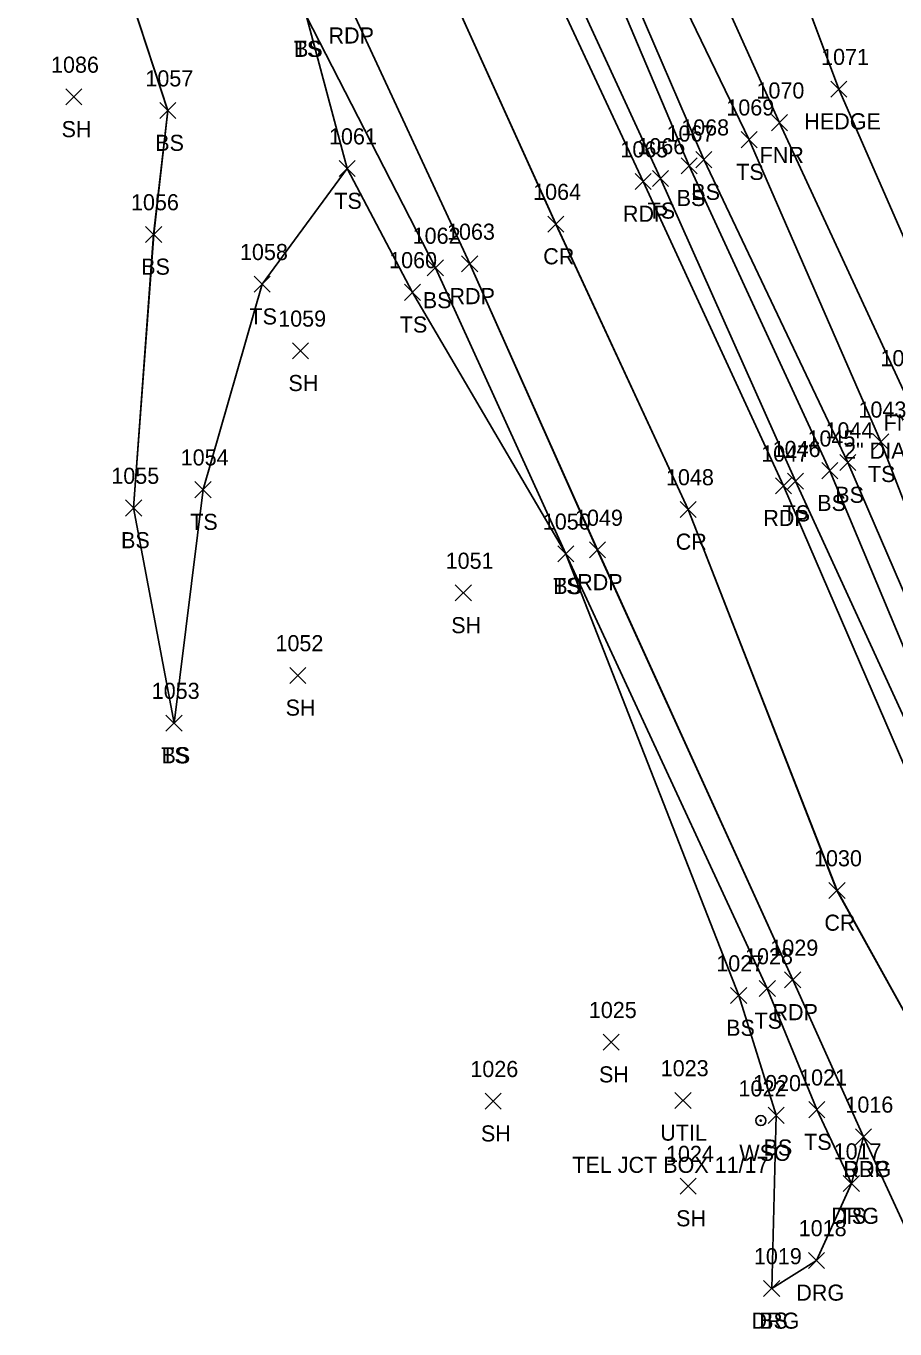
# Model space of a CAD drawing. Extents: x 1415642 to 1422021, y 544543 to 547232.
# Drawn here: x 1416485.4 to 1416593.3, y 546172.7 to 546334.5 of the extents above; entities that cross this region are included whole.
import ezdxf

# ---------------------------------------------------------------- set-up
doc = ezdxf.new("R2010")
doc.units = 0
for name, color, linetype in [('L_A', 7, 'Continuous'), ('L_I', 7, 'Continuous'), ('L_TIC', 7, 'Continuous'), ('LAHR', 7, 'Continuous'), ('LELB', 7, 'Continuous'), ('LFNC', 7, 'Continuous'), ('M_C', 7, 'Continuous'), ('P_A', 7, 'Continuous'), ('P_I', 7, 'Continuous'), ('P_TIC', 7, 'Continuous'), ('PET', 7, 'Continuous'), ('PRC', 7, 'Continuous'), ('R_A', 7, 'Continuous'), ('R_I', 7, 'Continuous'), ('R_TIC', 7, 'Continuous'), ('RDG', 7, 'Continuous'), ('U_A', 7, 'Continuous'), ('U_C', 7, 'Continuous'), ('U_I', 7, 'Continuous'), ('UDEFAULT', 7, 'Continuous'), ('UWV', 7, 'Continuous')]:
    doc.layers.add(name, color=color, linetype=linetype)

msp = doc.modelspace()

# ---------------------------------------------------------------- linework, layer by layer
at = {"layer": 'L_TIC'}
for points in [[(1416585.35, 546325.71), (1416587.35, 546327.71)], [(1416587.35, 546325.71), (1416585.35, 546327.71)], [(1416490.31, 546324.74), (1416492.31, 546326.74)], [(1416492.31, 546324.74), (1416490.31, 546326.74)], [(1416501.98, 546323.04), (1416503.98, 546325.04)], [(1416503.98, 546323.04), (1416501.98, 546325.04)], [(1416577.97, 546321.54), (1416579.97, 546323.54)], [(1416579.97, 546321.54), (1416577.97, 546323.54)], [(1416574.19, 546319.43), (1416576.19, 546321.43)], [(1416576.19, 546319.43), (1416574.19, 546321.43)], [(1416524.26, 546315.84), (1416526.26, 546317.84)], [(1416526.26, 546315.84), (1416524.26, 546317.84)], [(1416524.26, 546315.84), (1416526.26, 546317.84)], [(1416526.26, 546315.84), (1416524.26, 546317.84)], [(1416566.76, 546316.19), (1416568.76, 546318.19)], [(1416568.76, 546316.19), (1416566.76, 546318.19)], [(1416568.58, 546316.95), (1416570.58, 546318.95)], [(1416570.58, 546316.95), (1416568.58, 546318.95)], [(1416563.18, 546314.62), (1416565.18, 546316.62)], [(1416565.18, 546314.62), (1416563.18, 546316.62)], [(1416500.23, 546307.66), (1416502.23, 546309.66)], [(1416502.23, 546307.66), (1416500.23, 546309.66)], [(1416535.22, 546303.5), (1416537.22, 546305.5)], [(1416537.22, 546303.5), (1416535.22, 546305.5)], [(1416513.72, 546301.48), (1416515.72, 546303.48)], [(1416515.72, 546301.48), (1416513.72, 546303.48)], [(1416532.39, 546300.47), (1416534.39, 546302.47)], [(1416534.39, 546300.47), (1416532.39, 546302.47)], [(1416518.48, 546293.21), (1416520.48, 546295.21)], [(1416520.48, 546293.21), (1416518.48, 546295.21)], [(1416590.55, 546281.91), (1416592.55, 546283.91)], [(1416592.55, 546281.91), (1416590.55, 546283.91)], [(1416586.46, 546279.33), (1416588.46, 546281.33)], [(1416588.46, 546279.33), (1416586.46, 546281.33)], [(1416579.95, 546277.02), (1416581.95, 546279.02)], [(1416581.95, 546277.02), (1416579.95, 546279.02)], [(1416584.22, 546278.32), (1416586.22, 546280.32)], [(1416586.22, 546278.32), (1416584.22, 546280.32)], [(1416506.36, 546275.97), (1416508.36, 546277.97)], [(1416508.36, 546275.97), (1416506.36, 546277.97)], [(1416497.74, 546273.69), (1416499.74, 546275.69)], [(1416499.74, 546273.69), (1416497.74, 546275.69)], [(1416551.43, 546268), (1416553.43, 546270)], [(1416553.43, 546268), (1416551.43, 546270)], [(1416551.43, 546268), (1416553.43, 546270)], [(1416553.43, 546268), (1416551.43, 546270)], [(1416538.7, 546263.14), (1416540.7, 546265.14)], [(1416540.7, 546263.14), (1416538.7, 546265.14)], [(1416518.13, 546252.9), (1416520.13, 546254.9)], [(1416520.13, 546252.9), (1416518.13, 546254.9)], [(1416502.76, 546246.98), (1416504.76, 546248.98)], [(1416504.76, 546246.98), (1416502.76, 546248.98)], [(1416502.76, 546246.98), (1416504.76, 546248.98)], [(1416504.76, 546246.98), (1416502.76, 546248.98)], [(1416576.46, 546214.02), (1416578.46, 546216.02)], [(1416578.46, 546214.02), (1416576.46, 546216.02)], [(1416572.9, 546213.14), (1416574.9, 546215.14)], [(1416574.9, 546213.14), (1416572.9, 546215.14)], [(1416557.07, 546207.35), (1416559.07, 546209.35)], [(1416559.07, 546207.35), (1416557.07, 546209.35)], [(1416542.39, 546200.02), (1416544.39, 546202.02)], [(1416544.39, 546200.02), (1416542.39, 546202.02)], [(1416577.55, 546198.27), (1416579.55, 546200.27)], [(1416579.55, 546198.27), (1416577.55, 546200.27)], [(1416582.62, 546198.97), (1416584.62, 546200.97)], [(1416584.62, 546198.97), (1416582.62, 546200.97)], [(1416586.9, 546189.79), (1416588.9, 546191.79)], [(1416588.9, 546189.79), (1416586.9, 546191.79)], [(1416566.64, 546189.48), (1416568.64, 546191.48)], [(1416568.64, 546189.48), (1416566.64, 546191.48)], [(1416577, 546176.77), (1416579, 546178.77)], [(1416579, 546176.77), (1416577, 546178.77)]]:
    msp.add_lwpolyline(points, dxfattribs=at)
at = {"layer": 'LAHR'}
for points in [[(1416601.24, 546292.69), (1416586.35, 546326.71), (1416573.12, 546362.04), (1416558.49, 546390.29), (1416537.49, 546434.36), (1416523.93, 546467.1), (1416523.32, 546471.61)], [(1416601.24, 546292.69), (1416586.35, 546326.71), (1416573.12, 546362.03), (1416558.49, 546390.29), (1416537.49, 546434.36), (1416523.93, 546467.1), (1416523.32, 546471.61)]]:
    msp.add_lwpolyline(points, dxfattribs=at)
at = {"layer": 'LELB'}
for points in [[(1416578, 546177.77), (1416578.55, 546199.27), (1416573.9, 546214.14), (1416552.43, 546269), (1416536.22, 546304.5), (1416520.22, 546335.71), (1416500.65, 546371.21), (1416484.25, 546405.14), (1416455.06, 546455.78), (1416435.93, 546486.65), (1416412.14, 546519.01), (1416383.64, 546557.13), (1416352.74, 546592.54), (1416331.82, 546618.14), (1416293.94, 546655.61), (1416274.22, 546680.91), (1416245.72, 546708.98), (1416224.27, 546729.93), (1416198.14, 546753.3), (1416170.94, 546765.48), (1416158.5, 546767.31), (1416141.08, 546772.75), (1416136.01, 546776.95), (1416129, 546780.64)], [(1416578, 546177.77), (1416578.55, 546199.27), (1416573.9, 546214.14), (1416552.42, 546269.01), (1416536.22, 546304.5), (1416520.22, 546335.71), (1416500.65, 546371.22), (1416484.25, 546405.15), (1416455.06, 546455.79), (1416435.93, 546486.65), (1416412.14, 546519.01), (1416383.65, 546557.13), (1416352.74, 546592.54), (1416331.82, 546618.14), (1416293.94, 546655.62), (1416274.22, 546680.91), (1416245.72, 546708.98), (1416224.27, 546729.93), (1416198.14, 546753.3), (1416170.94, 546765.48), (1416158.51, 546767.31), (1416141.09, 546772.75), (1416136.01, 546776.96), (1416129.01, 546780.64)], [(1416503.76, 546247.98), (1416498.74, 546274.69), (1416501.23, 546308.66), (1416502.98, 546324.04), (1416489.47, 546365.32), (1416480.57, 546403.46), (1416453.11, 546455.02), (1416433.2, 546484.78), (1416409.26, 546516.78), (1416378.25, 546552.92), (1416343.61, 546583.91), (1416327.57, 546614.09), (1416289.4, 546651.59), (1416267.58, 546675.69), (1416237.14, 546697.31), (1416220.66, 546725.9), (1416195.41, 546750.9), (1416170.78, 546763.33), (1416158.82, 546764.49), (1416140.16, 546770.72), (1416135.4, 546775.05), (1416128.27, 546778.63)], [(1416503.76, 546247.98), (1416498.74, 546274.69), (1416501.24, 546308.65), (1416502.98, 546324.03), (1416489.47, 546365.32), (1416480.57, 546403.46), (1416453.11, 546455.02), (1416433.2, 546484.78), (1416409.26, 546516.79), (1416378.25, 546552.92), (1416343.61, 546583.91), (1416327.58, 546614.09), (1416289.4, 546651.59), (1416267.58, 546675.69), (1416237.14, 546697.31), (1416220.66, 546725.9), (1416195.42, 546750.9), (1416170.78, 546763.33), (1416158.81, 546764.5), (1416140.16, 546770.72), (1416135.4, 546775.05), (1416128.28, 546778.62)], [(1416587.9, 546190.79), (1416583.62, 546199.97), (1416577.46, 546215.02), (1416552.43, 546269), (1416533.39, 546301.47), (1416525.26, 546316.84), (1416520.22, 546335.71), (1416504.13, 546372.91), (1416486.87, 546406.07), (1416456.87, 546456.96), (1416435.93, 546486.65), (1416413.88, 546519.84), (1416385.73, 546558.12)], [(1416587.91, 546190.79), (1416583.61, 546199.97), (1416577.46, 546215.02), (1416552.42, 546269.01), (1416533.39, 546301.47), (1416525.26, 546316.84), (1416520.22, 546335.71), (1416504.13, 546372.91), (1416486.87, 546406.07), (1416456.87, 546456.96), (1416435.93, 546486.65), (1416413.88, 546519.84), (1416385.73, 546558.12)], [(1416624.83, 546188.33), (1416609.68, 546228.85), (1416587.46, 546280.33), (1416569.58, 546317.95), (1416555.08, 546351.62), (1416539.63, 546384.17), (1416546.45, 546386.59), (1416544.38, 546389.65), (1416537.72, 546389.11), (1416521.41, 546422.69), (1416507.02, 546457.32), (1416500.86, 546474.51), (1416499.33, 546475.96), (1416498.77, 546475.76), (1416499.17, 546473.82)], [(1416624.83, 546188.34), (1416609.68, 546228.85), (1416587.45, 546280.34), (1416569.58, 546317.95), (1416555.08, 546351.63), (1416539.63, 546384.17), (1416546.45, 546386.59), (1416544.38, 546389.64), (1416537.72, 546389.12), (1416521.42, 546422.68), (1416507.02, 546457.32), (1416500.87, 546474.51), (1416499.33, 546475.96), (1416498.77, 546475.76), (1416499.17, 546473.83)], [(1416624.13, 546188.48), (1416606.9, 546227.58), (1416585.22, 546279.32), (1416567.76, 546317.19), (1416553.66, 546350.45), (1416534.43, 546386.06), (1416517.2, 546422.02), (1416505.52, 546457.03), (1416499.17, 546473.83)], [(1416624.13, 546188.48), (1416606.9, 546227.58), (1416585.22, 546279.32), (1416567.76, 546317.19), (1416553.66, 546350.45), (1416534.43, 546386.06), (1416517.2, 546422.01), (1416505.52, 546457.03), (1416499.17, 546473.82)], [(1416620.93, 546187.09), (1416604.47, 546226.81), (1416580.95, 546278.02), (1416564.18, 546315.62), (1416549.05, 546348.52), (1416530.53, 546385.22), (1416512.89, 546419.96), (1416490.18, 546459.78)], [(1416620.93, 546187.09), (1416604.48, 546226.8), (1416580.95, 546278.02), (1416564.18, 546315.62), (1416549.05, 546348.51), (1416530.53, 546385.22), (1416512.89, 546419.96), (1416490.18, 546459.78)], [(1416632.67, 546189.86), (1416612.14, 546229.74), (1416591.55, 546282.91), (1416575.19, 546320.43), (1416559.06, 546353.84), (1416543.37, 546383.11), (1416547.74, 546382.96), (1416548.95, 546386.35)], [(1416632.67, 546189.86), (1416612.15, 546229.74), (1416591.55, 546282.91), (1416575.19, 546320.43), (1416559.06, 546353.84), (1416543.37, 546383.11), (1416547.74, 546382.97), (1416548.95, 546386.35)], [(1416503.76, 546247.98), (1416507.36, 546276.97), (1416514.72, 546302.48), (1416525.26, 546316.84)], [(1416503.76, 546247.98), (1416507.37, 546276.97), (1416514.72, 546302.48), (1416525.26, 546316.84)]]:
    msp.add_lwpolyline(points, dxfattribs=at)
at = {"layer": 'LFNC'}
for points in [[(1416616.17, 546291.53), (1416602.64, 546290.41), (1416594.37, 546289.3), (1416578.97, 546322.54), (1416563.77, 546356.27), (1416548.95, 546386.35), (1416547.3, 546389.95), (1416530.29, 546426.68), (1416513.55, 546462.2), (1416508.34, 546472.94), (1416504.48, 546483), (1416512.48, 546489.98)], [(1416616.17, 546291.53), (1416602.64, 546290.41), (1416594.37, 546289.3), (1416578.97, 546322.54), (1416563.77, 546356.27), (1416548.95, 546386.35), (1416547.3, 546389.95), (1416530.29, 546426.68), (1416513.55, 546462.2), (1416508.35, 546472.93), (1416504.48, 546483), (1416512.48, 546489.98)]]:
    msp.add_lwpolyline(points, dxfattribs=at)
at = {"layer": 'P_TIC'}
for points in [[(1416561.03, 546314.23), (1416563.03, 546316.23)], [(1416563.03, 546314.23), (1416561.03, 546316.23)], [(1416550.19, 546308.95), (1416552.19, 546310.95)], [(1416552.19, 546308.95), (1416550.19, 546310.95)], [(1416539.49, 546304), (1416541.49, 546306)], [(1416541.49, 546304), (1416539.49, 546306)], [(1416578.47, 546276.45), (1416580.47, 546278.45)], [(1416580.47, 546276.45), (1416578.47, 546278.45)], [(1416566.64, 546273.51), (1416568.64, 546275.51)], [(1416568.64, 546273.51), (1416566.64, 546275.51)], [(1416555.35, 546268.48), (1416557.35, 546270.48)], [(1416557.35, 546268.48), (1416555.35, 546270.48)], [(1416585.12, 546226.19), (1416587.12, 546228.19)], [(1416587.12, 546226.19), (1416585.12, 546228.19)], [(1416579.61, 546215.08), (1416581.61, 546217.08)], [(1416581.61, 546215.08), (1416579.61, 546217.08)], [(1416588.42, 546195.6), (1416590.42, 546197.6)], [(1416590.42, 546195.6), (1416588.42, 546197.6)]]:
    msp.add_lwpolyline(points, dxfattribs=at)
at = {"layer": 'PET'}
for points in [[(1416619.56, 546186.67), (1416601.63, 546226.16), (1416579.47, 546277.45), (1416562.03, 546315.23), (1416547.08, 546347.32), (1416527.73, 546384.04), (1416509.97, 546418.47), (1416487.43, 546457.37), (1416462.82, 546495.68), (1416435.56, 546537.44), (1416408.53, 546574.62)], [(1416619.56, 546186.67), (1416601.62, 546226.16), (1416579.47, 546277.45), (1416562.03, 546315.23), (1416547.08, 546347.32), (1416527.73, 546384.03), (1416509.97, 546418.46), (1416487.43, 546457.37), (1416462.82, 546495.68), (1416435.56, 546537.44), (1416408.53, 546574.61)], [(1416599.36, 546175.05), (1416589.42, 546196.6), (1416580.61, 546216.08), (1416556.35, 546269.48), (1416540.49, 546305), (1416525.46, 546337.37), (1416506.55, 546374.02), (1416489.16, 546406.45), (1416459.13, 546457.37), (1416438.7, 546488.16), (1416417.68, 546520.98), (1416388.9, 546560.28)], [(1416599.36, 546175.05), (1416589.42, 546196.6), (1416580.62, 546216.08), (1416556.34, 546269.48), (1416540.49, 546305), (1416525.46, 546337.38), (1416506.55, 546374.02), (1416489.16, 546406.45), (1416459.13, 546457.38), (1416438.7, 546488.17), (1416417.68, 546520.98), (1416388.9, 546560.28)]]:
    msp.add_lwpolyline(points, dxfattribs=at)
at = {"layer": 'PRC'}
for points in [[(1416610.25, 546183.67), (1416586.12, 546227.19), (1416567.64, 546274.51), (1416551.19, 546309.95), (1416536.28, 546342.88), (1416517.21, 546379.83), (1416500.09, 546412.89), (1416469.99, 546464.05), (1416448.59, 546494.95), (1416427.64, 546528.31), (1416425.29, 546532.23), (1416399.16, 546568.17)], [(1416610.26, 546183.67), (1416586.11, 546227.19), (1416567.64, 546274.51), (1416551.18, 546309.96), (1416536.27, 546342.88), (1416517.21, 546379.83), (1416500.09, 546412.89), (1416469.99, 546464.05), (1416448.59, 546494.95), (1416427.64, 546528.31), (1416425.29, 546532.24), (1416399.16, 546568.17)]]:
    msp.add_lwpolyline(points, dxfattribs=at)
at = {"layer": 'R_TIC'}
for points in [[(1416588.42, 546195.6), (1416590.42, 546197.6)], [(1416590.42, 546195.6), (1416588.42, 546197.6)], [(1416586.9, 546189.79), (1416588.9, 546191.79)], [(1416588.9, 546189.79), (1416586.9, 546191.79)], [(1416582.57, 546180.25), (1416584.57, 546182.25)], [(1416584.57, 546180.25), (1416582.57, 546182.25)], [(1416577, 546176.77), (1416579, 546178.77)], [(1416579, 546176.77), (1416577, 546178.77)]]:
    msp.add_lwpolyline(points, dxfattribs=at)
at = {"layer": 'RDG'}
for points in [[(1416589.42, 546196.6), (1416587.9, 546190.79), (1416583.57, 546181.25), (1416578, 546177.77)], [(1416589.42, 546196.6), (1416587.91, 546190.79), (1416583.57, 546181.25), (1416578, 546177.77)]]:
    msp.add_lwpolyline(points, dxfattribs=at)
at = {"layer": 'UDEFAULT'}
for points in [[(1416565.99, 546200.12), (1416567.99, 546202.12)], [(1416567.99, 546200.12), (1416565.99, 546202.12)]]:
    msp.add_lwpolyline(points, dxfattribs=at)
at = {"layer": 'UWV'}
for radius in [0.625, 0.0833]:
    msp.add_circle((1416576.65, 546198.61), radius, dxfattribs=at)

# ---------------------------------------------------------------- texts
at = {"layer": 'L_A'}
for s, p in [('TS', (1416518.63, 546330.71)), ('BS', (1416518.66, 546330.71)), ('SH', (1416489.79, 546320.74)), ('HEDGE', (1416582.05, 546321.71)), ('BS', (1416501.42, 546319.04)), ('FNR', (1416576.5, 546317.54)), ('TS', (1416573.6, 546315.43)), ('BS', (1416568.02, 546312.95)), ('TS', (1416523.67, 546311.84)), ('TS', (1416523.67, 546311.84)), ('BS', (1416566.2, 546312.19)), ('TS', (1416562.59, 546310.62)), ('BS', (1416499.68, 546303.66)), ('BS', (1416534.66, 546299.5)), ('TS', (1416513.13, 546297.48)), ('TS', (1416531.8, 546296.47)), ('SH', (1416517.97, 546289.21)), ('FNR', (1416591.91, 546284.3)), ('TS', (1416589.96, 546277.91)), ('BS', (1416583.66, 546274.32)), ('BS', (1416585.9, 546275.33)), ('TS', (1416579.36, 546273.02)), ('TS', (1416505.77, 546271.97)), ('BS', (1416497.18, 546269.69)), ('TS', (1416550.84, 546264)), ('BS', (1416550.87, 546264)), ('SH', (1416538.19, 546259.14)), ('SH', (1416517.62, 546248.9)), ('TS', (1416502.17, 546242.98)), ('BS', (1416502.2, 546242.98)), ('BS', (1416572.34, 546209.14)), ('TS', (1416575.87, 546210.02)), ('SH', (1416556.55, 546203.35)), ('SH', (1416541.88, 546196.02)), ('TS', (1416582.03, 546194.97)), ('BS', (1416576.99, 546194.27)), ('SH', (1416566.13, 546185.48)), ('TS', (1416586.31, 546185.79)), ('BS', (1416576.44, 546172.77))]:
    msp.add_text(s, height=2, dxfattribs=at).set_placement(p)
at = {"layer": 'L_I'}
for s, p in [('1071', (1416584.14, 546329.71)), ('1086', (1416488.48, 546328.74)), ('1057', (1416500.2, 546327.04)), ('1070', (1416576.11, 546325.54)), ('1069', (1416572.37, 546323.43)), ('1068', (1416566.76, 546320.95)), ('1061', (1416523.01, 546319.84)), ('1061', (1416523.01, 546319.84)), ('1067', (1416564.94, 546320.19)), ('1066', (1416561.31, 546318.62)), ('1056', (1416498.41, 546311.66)), ('1062', (1416533.4, 546307.5)), ('1058', (1416511.95, 546305.48)), ('1060', (1416530.48, 546304.47)), ('1059', (1416516.7, 546297.21)), ('1040', (1416591.51, 546292.3)), ('1043', (1416588.78, 546285.91)), ('1045', (1416582.45, 546282.32)), ('1044', (1416584.68, 546283.33)), ('1046', (1416578.12, 546281.02)), ('1054', (1416504.59, 546279.97)), ('1055', (1416495.97, 546277.69)), ('1050', (1416549.57, 546272)), ('1050', (1416549.57, 546272)), ('1051', (1416537.5, 546267.14)), ('1052', (1416516.36, 546256.9)), ('1053', (1416500.99, 546250.98)), ('1053', (1416500.99, 546250.98)), ('1027', (1416571.12, 546217.14)), ('1028', (1416574.69, 546218.02)), ('1025', (1416555.29, 546211.35)), ('1026', (1416540.57, 546204.02)), ('1021', (1416581.41, 546202.97)), ('1020', (1416575.69, 546202.27)), ('1024', (1416564.87, 546193.48)), ('1017', (1416585.7, 546193.79)), ('1019', (1416575.79, 546180.77))]:
    msp.add_text(s, height=2, dxfattribs=at).set_placement(p)
at = {"layer": 'M_C'}
msp.add_text('2" DIA 12"ABG', height=2, dxfattribs=at).set_placement((1416587, 546280.8))
at = {"layer": 'P_A'}
for s, p in [('RDP', (1416522.95, 546332.37)), ('RDP', (1416559.52, 546310.23)), ('CR', (1416549.62, 546304.95)), ('RDP', (1416537.98, 546300)), ('RDP', (1416576.96, 546272.45)), ('CR', (1416566.08, 546269.51)), ('RDP', (1416553.84, 546264.48)), ('CR', (1416584.55, 546222.19)), ('RDP', (1416578.1, 546211.08)), ('RDP', (1416586.91, 546191.6))]:
    msp.add_text(s, height=2, dxfattribs=at).set_placement(p)
at = {"layer": 'P_I'}
for s, p in [('1065', (1416559.21, 546318.23)), ('1064', (1416548.37, 546312.95)), ('1063', (1416537.67, 546308)), ('1047', (1416576.7, 546280.45)), ('1048', (1416564.87, 546277.51)), ('1049', (1416553.57, 546272.48)), ('1030', (1416583.26, 546230.19)), ('1029', (1416577.84, 546219.08)), ('1016', (1416587.16, 546199.6))]:
    msp.add_text(s, height=2, dxfattribs=at).set_placement(p)
at = {"layer": 'R_A'}
for p in [(1416586.91, 546191.6), (1416585.39, 546185.79), (1416581.06, 546176.25), (1416575.49, 546172.77)]:
    msp.add_text('DRG', height=2, dxfattribs=at).set_placement(p)
at = {"layer": 'R_I'}
for s, p in [('1016', (1416587.16, 546199.6)), ('1017', (1416585.7, 546193.79)), ('1018', (1416581.36, 546184.25)), ('1019', (1416575.79, 546180.77))]:
    msp.add_text(s, height=2, dxfattribs=at).set_placement(p)
at = {"layer": 'U_A'}
for s, p in [('UTIL', (1416564.16, 546196.12)), ('WSO', (1416573.98, 546193.61))]:
    msp.add_text(s, height=2, dxfattribs=at).set_placement(p)
at = {"layer": 'U_C'}
msp.add_text('TEL JCT BOX 11/17', height=2, dxfattribs=at).set_placement((1416553.23, 546192.12))
at = {"layer": 'U_I'}
for s, p in [('1023', (1416564.22, 546204.12)), ('1022', (1416573.88, 546201.61))]:
    msp.add_text(s, height=2, dxfattribs=at).set_placement(p)

doc.saveas('drawing.dxf')
